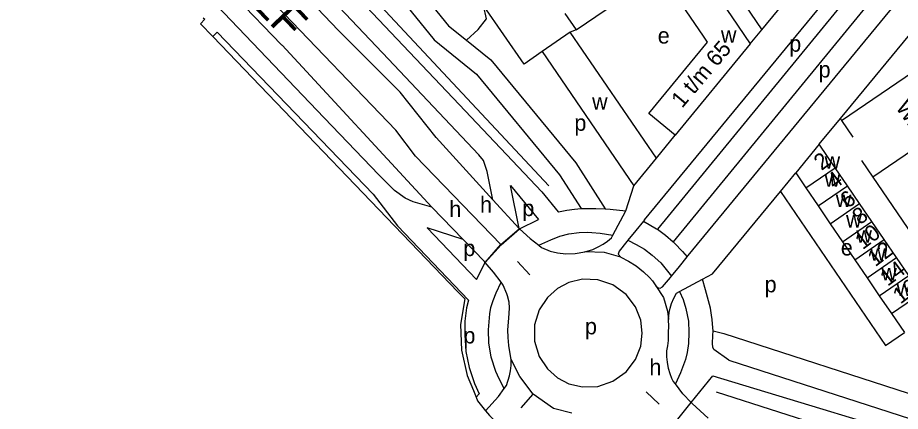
# Model space of a CAD drawing. Extents: x 154320 to 156262, y 382651 to 384180.
# Drawn here: x 155334.5 to 155553.7, y 382837.8 to 382935.5 of the extents above; entities that cross this region are included whole.
import ezdxf

# ---------------------------------------------------------------- set-up
doc = ezdxf.new("R2010")
doc.units = 0
for name, color, linetype in [('BLT_Basislijn', 7, 'Continuous'), ('BLT_Bebouwing', 7, 'Continuous'), ('BLT_Centroide', 7, 'Continuous'), ('BLT_Gemeentegrens', 7, 'Continuous'), ('BLT_Huisnummer', 7, 'Continuous'), ('BLT_Huisnummer_ tussenligend', 7, 'Continuous'), ('BLT_Huisnummer_reeks', 7, 'Continuous'), ('BLT_Onderverdeling_panden', 7, 'Continuous'), ('BLT_Straatnaam', 7, 'Continuous'), ('BLT_Straatnaam_hoofdweg', 7, 'Continuous'), ('BLT_Vlakafsluiter', 7, 'Continuous')]:
    doc.layers.add(name, color=color, linetype=linetype)

msp = doc.modelspace()

# ---------------------------------------------------------------- linework, layer by layer
at = {"layer": 'BLT_Basislijn'}
for p, q in [((155571.04, 382977.72), (155493.33, 382883.01)), ((155490.16, 382885.35), (155564.44, 382975.53)), ((155575.3, 382975.04), (155497.24, 382879.9)), ((155501, 382876.48), (155575.24, 382966.64)), ((155499.84, 382961.01), (155519.27, 382932.51)), ((155371.68, 382958.14), (155400, 382928.83)), ((155519.27, 382932.51), (155530.86, 382946.57)), ((155538.78, 382910.52), (155558.88, 382934.84)), ((155473.13, 382932.51), (155471.71, 382931.92)), ((155516.39, 382929.02), (155519.27, 382932.51)), ((155382.91, 382930.86), (155384.02, 382931.92)), ((155445.9, 382929.94), (155451.94, 382925.07)), ((155400, 382928.83), (155400.12, 382928.7)), ((155400.12, 382928.7), (155437.28, 382888.54)), ((155539.09, 382910.05), (155564.14, 382927.16)), ((155574.39, 382914.89), (155546.87, 382895.92)), ((155533.48, 382904.12), (155538.78, 382910.52)), ((155493.08, 382900.66), (155497.76, 382906.34)), ((155523.87, 382892.37), (155527.69, 382897.01)), ((155456.87, 382893.89), (155463.77, 382885.45)), ((155485.48, 382887.57), (155487.46, 382893.83)), ((155464.6, 382892.33), (155468.7, 382887.31)), ((155507, 382871.93), (155523.87, 382892.37)), ((155437.28, 382888.54), (155445.1, 382880.46)), ((155474.42, 382888.14), (155475.82, 382888.17)), ((155475.82, 382888.17), (155478.07, 382888.17)), ((155478.07, 382888.17), (155480.38, 382888.1)), ((155468.7, 382887.31), (155468.81, 382887.34)), ((155468.81, 382887.34), (155470.81, 382887.73)), ((155470.81, 382887.73), (155472.71, 382888)), ((155472.71, 382888), (155474.42, 382888.14)), ((155480.38, 382888.1), (155481.6, 382888.05)), ((155481.6, 382888.05), (155485.48, 382887.57)), ((155482.26, 382881.53), (155485.48, 382887.57)), ((155428.76, 382883.86), (155446.39, 382865.45)), ((155459.07, 382883.11), (155463.77, 382885.45)), ((155489.88, 382885.01), (155487.99, 382882.71)), ((155490.16, 382885.35), (155489.88, 382885.01)), ((155489.88, 382885.01), (155493.15, 382883.14)), ((155436.14, 382883.38), (155448.41, 382870.57)), ((155469.12, 382881.28), (155471.3, 382881.86)), ((155471.3, 382881.86), (155473.92, 382882.21)), ((155473.92, 382882.21), (155475.93, 382882.26)), ((155475.93, 382882.26), (155477.02, 382882.25)), ((155477.02, 382882.25), (155479.16, 382882.06)), ((155479.16, 382882.06), (155482.26, 382881.53)), ((155487.99, 382882.71), (155486, 382880.28)), ((155493.15, 382883.14), (155493.33, 382883.01)), ((155493.33, 382883.01), (155495.31, 382881.58)), ((155445.1, 382880.46), (155450.37, 382874.98)), ((155461.7, 382880.76), (155463.87, 382879.05)), ((155463.87, 382879.05), (155466.83, 382880.43)), ((155466.83, 382880.43), (155469.12, 382881.28)), ((155479.86, 382879.3), (155480.94, 382880.09)), ((155480.94, 382880.09), (155481.92, 382880.89)), ((155481.92, 382880.89), (155482.26, 382881.53)), ((155485.76, 382879.98), (155483.85, 382877.6)), ((155486, 382880.28), (155485.76, 382879.98)), ((155486, 382880.28), (155488.02, 382879.28)), ((155495.31, 382881.58), (155497.24, 382879.9)), ((155497.24, 382879.9), (155497.56, 382879.61)), ((155497.56, 382879.61), (155499.59, 382877.5)), ((155463.87, 382879.05), (155464.59, 382878.49)), ((155464.59, 382878.49), (155466.73, 382877.58)), ((155466.73, 382877.58), (155468.5, 382877.16)), ((155472.94, 382876.97), (155475.34, 382877.38)), ((155475.34, 382877.38), (155477.3, 382878.01)), ((155477.3, 382878.01), (155478.66, 382878.62)), ((155478.66, 382878.62), (155479.86, 382879.3)), ((155483.85, 382877.6), (155483.63, 382876.82)), ((155488.02, 382879.28), (155490.17, 382878.05)), ((155490.17, 382878.05), (155492.04, 382876.56)), ((155499.59, 382877.5), (155500.73, 382876.15)), ((155468.5, 382877.16), (155470.62, 382876.95)), ((155470.62, 382876.95), (155472.94, 382876.97)), ((155483.63, 382876.82), (155484.22, 382876.1)), ((155484.22, 382876.1), (155486.14, 382875.11)), ((155486.14, 382875.11), (155488.08, 382873.91)), ((155492.04, 382876.56), (155494.16, 382874.66)), ((155498.82, 382873.8), (155500.73, 382876.15)), ((155500.73, 382876.15), (155501, 382876.48)), ((155448.41, 382870.57), (155450.56, 382874.76)), ((155450.53, 382874.8), (155450.37, 382874.98)), ((155450.56, 382874.76), (155450.53, 382874.8)), ((155452.67, 382872.38), (155450.56, 382874.76)), ((155461.67, 382871.75), (155458.55, 382874.98)), ((155488.08, 382873.91), (155489.92, 382872.45)), ((155494.16, 382874.66), (155496.87, 382871.41)), ((155496.87, 382871.41), (155498.82, 382873.8)), ((155454.5, 382869.91), (155452.67, 382872.38)), ((155489.92, 382872.45), (155491.33, 382871.06)), ((155491.33, 382871.06), (155492.08, 382870.18)), ((155494.64, 382868.75), (155496.58, 382871.06)), ((155496.58, 382871.06), (155496.87, 382871.41)), ((155504.53, 382870.61), (155507, 382871.93)), ((155453.32, 382867.22), (155454.5, 382869.91)), ((155455.06, 382869.16), (155454.5, 382869.91)), ((155455.93, 382866.98), (155455.06, 382869.16)), ((155492.08, 382870.18), (155492.95, 382869.02)), ((155492.95, 382869.02), (155493.55, 382868.5)), ((155493.55, 382868.5), (155494.02, 382868.39)), ((155494.02, 382868.39), (155494.64, 382868.75)), ((155498.81, 382867.56), (155504.53, 382870.61)), ((155505.25, 382867.98), (155504.53, 382870.61)), ((155452.54, 382865.36), (155453.32, 382867.22)), ((155456.14, 382866.46), (155455.93, 382866.98)), ((155456.48, 382864.93), (155456.14, 382866.46)), ((155497.43, 382865.88), (155498.09, 382867.17)), ((155498.09, 382867.17), (155498.81, 382867.56)), ((155498.81, 382867.56), (155499.71, 382865.55)), ((155506.5, 382863.45), (155505.25, 382867.98)), ((155451.99, 382863.57), (155452.54, 382865.36)), ((155456.61, 382863.56), (155456.48, 382864.93)), ((155496.5, 382863.46), (155496.81, 382864.6)), ((155496.81, 382864.6), (155497.43, 382865.88)), ((155499.71, 382865.55), (155500.42, 382863.32)), ((155451.35, 382858.05), (155451.69, 382862.01)), ((155451.69, 382862.01), (155451.99, 382863.57)), ((155456.33, 382859.97), (155456.5, 382862.1)), ((155456.5, 382862.1), (155456.61, 382863.56)), ((155496.09, 382860.6), (155496.22, 382862.37)), ((155496.22, 382862.37), (155496.5, 382863.46)), ((155500.42, 382863.32), (155501.04, 382860.18)), ((155506.77, 382861.67), (155506.5, 382863.45)), ((155456.22, 382858.03), (155456.33, 382859.97)), ((155496.14, 382858.85), (155496.09, 382860.6)), ((155501.04, 382860.18), (155501.14, 382857.43)), ((155506.93, 382860.63), (155506.77, 382861.67)), ((155451.43, 382854.8), (155451.35, 382858.05)), ((155456.25, 382856.19), (155456.22, 382858.03)), ((155496.13, 382857.44), (155496.14, 382858.85)), ((155456.4, 382854.15), (155456.25, 382856.19)), ((155495.89, 382854.12), (155496.06, 382855.37)), ((155496.06, 382855.37), (155496.11, 382856.54)), ((155496.11, 382856.54), (155496.13, 382857.44)), ((155501.14, 382857.43), (155501.09, 382854.63)), ((155452.01, 382851.29), (155451.43, 382854.8)), ((155456.75, 382852.13), (155456.4, 382854.15)), ((155495.7, 382852.85), (155495.89, 382854.12)), ((155501.09, 382854.63), (155500.7, 382852.45)), ((155507.06, 382853.76), (155507.01, 382854.65)), ((155507.38, 382853.14), (155507.06, 382853.76)), ((155511.04, 382850.51), (155507.38, 382853.14)), ((155453.18, 382847.71), (155452.01, 382851.29)), ((155457, 382850.69), (155456.75, 382852.13)), ((155495.67, 382851.35), (155495.7, 382852.85)), ((155495.8, 382850), (155495.67, 382851.35)), ((155500.7, 382852.45), (155500.28, 382850.7)), ((155456.87, 382847.89), (155457, 382849.21)), ((155457, 382849.21), (155457, 382850.69)), ((155496.09, 382848.42), (155495.8, 382850)), ((155500.28, 382850.7), (155499.04, 382847.35)), ((155511.04, 382850.51), (155566.62, 382832.56)), ((155454, 382845.86), (155453.18, 382847.71)), ((155455.88, 382844.28), (155456.57, 382846.68)), ((155456.57, 382846.68), (155456.87, 382847.89)), ((155496.48, 382847.14), (155496.09, 382848.42)), ((155496.94, 382845.98), (155496.48, 382847.14)), ((155499.04, 382847.35), (155497.79, 382844.63)), ((155501.74, 382840.01), (155507.06, 382846.63)), ((155455.32, 382843.5), (155454, 382845.86)), ((155497.24, 382845.34), (155496.94, 382845.98)), ((155497.79, 382844.63), (155497.24, 382845.34)), ((155499.68, 382842.17), (155497.79, 382844.63)), ((155453.89, 382841.55), (155455.32, 382843.5)), ((155455.32, 382843.5), (155455.88, 382844.28)), ((155493.81, 382839.6), (155490.56, 382842.71)), ((155501.74, 382840.01), (155499.68, 382842.17)), ((155507.93, 382842.69), (155597.71, 382813.99)), ((155459.48, 382838.69), (155462.45, 382842.06)), ((155501.97, 382839.77), (155501.74, 382840.01)), ((155505.9, 382836.13), (155501.97, 382839.77))]:
    msp.add_line(p, q, dxfattribs=at)
for points in [[(155452.48, 382890.34), (155451.08, 382897.36), (155450.16, 382900.07), (155449.01, 382901.52), (155440.46, 382910.55), (155426.53, 382925.2), (155374.6, 382980.08), (155368.26, 382988), (155363.39, 382996.14), (155359.25, 383004.63), (155355.88, 383013.44), (155353.21, 383023.73), (155351.64, 383034.45), (155350.76, 383045.31), (155349.91, 383053.88), (155348.58, 383062.03), (155347.18, 383068.49), (155343.2, 383080.69), (155338.57, 383091.19), (155333.17, 383101.45)], [(155464.6, 382892.33), (155444.09, 382913.99), (155430.16, 382928.64), (155378.37, 382983.36), (155372.37, 382990.86), (155367.79, 382998.53), (155363.84, 383006.62), (155360.65, 383014.97), (155358.12, 383024.73), (155356.61, 383035.02), (155355.74, 383045.76), (155354.87, 383054.53), (155353.49, 383062.96), (155352.01, 383069.8)], [(155437.28, 382888.54), (155432.69, 382889.83), (155430.73, 382890.72), (155428.07, 382892.62), (155424.14, 382896.55), (155410.6, 382910.72), (155326.81, 382998.3), (155279.11, 383048.25)], [(155359.43, 383050.26), (155360.11, 383033.83), (155360.7, 383030.48), (155362.25, 383022.78), (155363.35, 383018.87), (155367.09, 383009.15), (155368.62, 383005.19), (155373.95, 382995.75), (155382.51, 382983.65), (155393.52, 382971.73), (155466.33, 382893.76)], [(155454.47, 382879.21), (155433.3, 382901.13), (155428.38, 382907.64), (155368.92, 382969.61)], [(155427.83, 382950.42), (155441.42, 382933.55), (155445.9, 382929.94)], [(155423.55, 382947.76), (155437.87, 382930), (155448.41, 382921.49), (155469.06, 382896.53), (155474.42, 382888.14)], [(155452.48, 382890.34), (155438.41, 382905.8), (155429.45, 382917.01), (155414.1, 382932.37), (155400.12, 382947.12)], [(155445.9, 382929.94), (155448.86, 382932.57), (155450.91, 382935.26), (155450.14, 382938.57)], [(155464.7, 382927.12), (155460.22, 382924.02), (155450.14, 382938.57)], [(155422.76, 382891.7), (155384.02, 382931.92)], [(155451.94, 382925.07), (155473.11, 382899.48), (155480.38, 382888.1)], [(155546.87, 382895.92), (155566.51, 382867.1), (155588.7, 382893.95), (155574.39, 382914.89)], [(155538.78, 382910.52), (155539.09, 382910.05)], [(155539.09, 382910.05), (155541.89, 382905.87)], [(155544.04, 382900.08), (155546.87, 382895.92)], [(155459, 382883.17), (155456.87, 382893.89)], [(155422.76, 382891.7), (155428.76, 382883.86)], [(155523.87, 382892.37), (155549.96, 382854.2), (155554.67, 382857.36)], [(155459, 382883.17), (155452.48, 382890.34)], [(155445.1, 382880.46), (155436.14, 382883.38)], [(155459.03, 382883.14), (155459, 382883.17)], [(155459.07, 382883.11), (155459.03, 382883.14)], [(155461.7, 382880.76), (155459.07, 382883.11)], [(155454.5, 382879.17), (155454.47, 382879.21)], [(155489.59, 382857.24), (155489.21, 382860.45), (155487.89, 382863.79), (155485.54, 382866.87), (155482.28, 382869.21), (155478.5, 382870.48), (155474.71, 382870.61), (155471.33, 382869.8), (155468.55, 382868.34), (155466.04, 382866.11), (155464.01, 382863.03), (155462.85, 382859.26), (155462.85, 382855.23), (155464.01, 382851.46), (155466.04, 382848.38), (155468.55, 382846.15), (155471.33, 382844.69), (155474.71, 382843.88), (155478.5, 382844.01), (155482.28, 382845.28), (155485.54, 382847.62), (155487.89, 382850.7), (155489.21, 382854.04), (155489.59, 382857.24)], [(155446.39, 382865.45), (155445.9, 382863.52), (155445.53, 382860.19), (155445.47, 382856.84), (155445.74, 382852.72), (155446.57, 382848.67), (155447.9, 382844.76), (155449.11, 382842.18)], [(155507.14, 382857.77), (155507.12, 382858.58), (155506.93, 382860.63)], [(155507.01, 382854.65), (155507.12, 382856.65), (155507.14, 382857.77)], [(155507.14, 382857.77), (155509.86, 382857.17), (155558.41, 382841.39), (155564.32, 382842.97)], [(155507.06, 382846.63), (155568.29, 382828.1)], [(155448.32, 382841.33), (155449.11, 382842.18)], [(155450.64, 382837.98), (155453.89, 382841.55)]]:
    msp.add_lwpolyline(points, dxfattribs=at)
at = {"layer": 'BLT_Bebouwing'}
for p, q in [((155473.13, 382932.51), (155480.59, 382937.6)), ((155471.71, 382931.92), (155464.7, 382927.12)), ((155493.08, 382900.66), (155471.71, 382931.92)), ((155516.39, 382929.02), (155497.76, 382906.34)), ((155464.7, 382927.12), (155487.46, 382893.83)), ((155537.47, 382898.28), (155533.48, 382904.12)), ((155487.46, 382893.83), (155493.08, 382900.66)), ((155527.69, 382897.01), (155530.21, 382893.3)), ((155540.52, 382893.83), (155537.47, 382898.28)), ((155530.21, 382893.3), (155533.25, 382888.84)), ((155543.55, 382889.39), (155540.52, 382893.83)), ((155533.25, 382888.84), (155536.27, 382884.4)), ((155536.27, 382884.4), (155539.33, 382879.91)), ((155549.67, 382880.44), (155546.61, 382884.91)), ((155552.71, 382875.99), (155549.67, 382880.44)), ((155542.38, 382875.43), (155545.41, 382870.97)), ((155555.76, 382871.54), (155552.71, 382875.99)), ((155545.41, 382870.97), (155548.44, 382866.52)), ((155548.44, 382866.52), (155551.45, 382862.1))]:
    msp.add_line(p, q, dxfattribs=at)
for points in [[(155493.82, 382947.01), (155500.85, 382951.81), (155511.82, 382935.73), (155516.39, 382929.02)], [(155497.76, 382906.34), (155491.19, 382911.74), (155505.78, 382929.47), (155504.79, 382930.92), (155493.82, 382947.01)], [(155470.37, 382936.55), (155473.13, 382932.51)], [(155533.48, 382904.12), (155527.69, 382897.01)], [(155546.61, 382884.91), (155543.55, 382889.39)], [(155539.33, 382879.91), (155542.38, 382875.43)], [(155551.45, 382862.1), (155554.67, 382857.36)]]:
    msp.add_lwpolyline(points, dxfattribs=at)
at = {"layer": 'BLT_Gemeentegrens'}
for points in [[(155380.57, 382935.54), (155380.97, 382935.13), (155379.84, 382934.05), (155382.91, 382930.86)], [(155382.91, 382930.86), (155443.75, 382867.51), (155445.47, 382865.72), (155444.47, 382859.39), (155444.69, 382852.98), (155446.11, 382846.73), (155447.63, 382843.01), (155448.32, 382841.33)], [(155448.32, 382841.33), (155448.68, 382840.46), (155450.64, 382837.98)], [(155450.64, 382837.98), (155451.6, 382836.77), (155454.78, 382833.58)]]:
    msp.add_lwpolyline(points, dxfattribs=at)
at = {"layer": 'BLT_Onderverdeling_panden'}
for p, q in [((155530.21, 382893.3), (155537.47, 382898.28)), ((155533.25, 382888.84), (155540.52, 382893.83)), ((155536.27, 382884.4), (155543.55, 382889.39)), ((155539.33, 382879.91), (155546.61, 382884.91)), ((155542.38, 382875.43), (155549.67, 382880.44)), ((155545.41, 382870.97), (155552.71, 382875.99)), ((155548.44, 382866.52), (155555.76, 382871.54)), ((155551.45, 382862.1), (155558.77, 382867.13))]:
    msp.add_line(p, q, dxfattribs=at)
at = {"layer": 'BLT_Vlakafsluiter'}
for p, q in [((155454.47, 382879.21), (155459.03, 382883.14)), ((155454.5, 382879.17), (155459.07, 382883.11)), ((155450.53, 382874.8), (155454.47, 382879.21)), ((155450.56, 382874.76), (155454.5, 382879.17)), ((155480.22, 382877.26), (155475.34, 382877.38)), ((155484.22, 382876.1), (155480.22, 382877.26)), ((155492.95, 382869.02), (155494.82, 382866.07)), ((155494.82, 382866.07), (155495.86, 382862.72)), ((155495.86, 382862.72), (155496.09, 382860.6)), ((155459.13, 382846.44), (155457, 382850.69)), ((155462.45, 382842.06), (155459.13, 382846.44)), ((155467.53, 382838.55), (155462.45, 382842.06)), ((155498.11, 382835.49), (155501.74, 382840.01)), ((155472.12, 382837.39), (155467.53, 382838.55))]:
    msp.add_line(p, q, dxfattribs=at)

# ---------------------------------------------------------------- texts
at = {"layer": 'BLT_Centroide'}
for s, p in [('e', (155493.42, 382929.11)), ('w', (155509.11, 382929.31)), ('p', (155526.07, 382927.09)), ('p', (155533.37, 382920.68)), ('w', (155477.11, 382912.73)), ('p', (155472.72, 382907.46)), ('w', (155534.85, 382898.04)), ('w', (155534.85, 382893.57)), ('h', (155449.28, 382887.15)), ('w', (155537.64, 382888.52)), ('h', (155441.65, 382886.04)), ('p', (155459.8, 382886.29)), ('w', (155540.19, 382883.45)), ('w', (155542.74, 382879.68)), ('p', (155445.14, 382876.36)), ('e', (155538.88, 382876.52)), ('w', (155546.17, 382875.24)), ('w', (155548.94, 382870.36)), ('p', (155519.96, 382867.37)), ('w', (155552.71, 382866.48)), ('p', (155475.35, 382856.94)), ('p', (155445.16, 382854.67)), ('h', (155491.34, 382846.8))]:
    msp.add_text(s, height=4, dxfattribs=at).set_placement(p)
at = {"layer": 'BLT_Huisnummer'}
for s, p in [('2', (155534.09, 382897.46)), ('6', (155540.6, 382888.05)), ('10', (155544.31, 382877.81)), ('14', (155550.51, 382868.73))]:
    msp.add_text(s, height=4, rotation=36.8685, dxfattribs=at).set_placement(p)
at = {"layer": 'BLT_Huisnummer_ tussenligend'}
for s, p in [('4', (155537.33, 382892.79)), ('8', (155543.62, 382883.97)), ('12', (155547.43, 382873.57)), ('16', (155553.69, 382864.32))]:
    msp.add_text(s, height=4, rotation=36.8685, dxfattribs=at).set_placement(p)
at = {"layer": 'BLT_Huisnummer_reeks'}
msp.add_text('1 t/m 65', height=4, rotation=49.8685, dxfattribs=at).set_placement((155499.47, 382912.91))
at = {"layer": 'BLT_Straatnaam'}
msp.add_text('WATERLINIE', height=4, rotation=306.0883, dxfattribs=at).set_placement((155552.33, 382913.24))
at = {"layer": 'BLT_Straatnaam_hoofdweg'}
msp.add_text('MEERHOVENDREEF', height=8, rotation=313.7994, dxfattribs=at).set_placement((155328.39, 383005.47))

doc.saveas('drawing.dxf')
